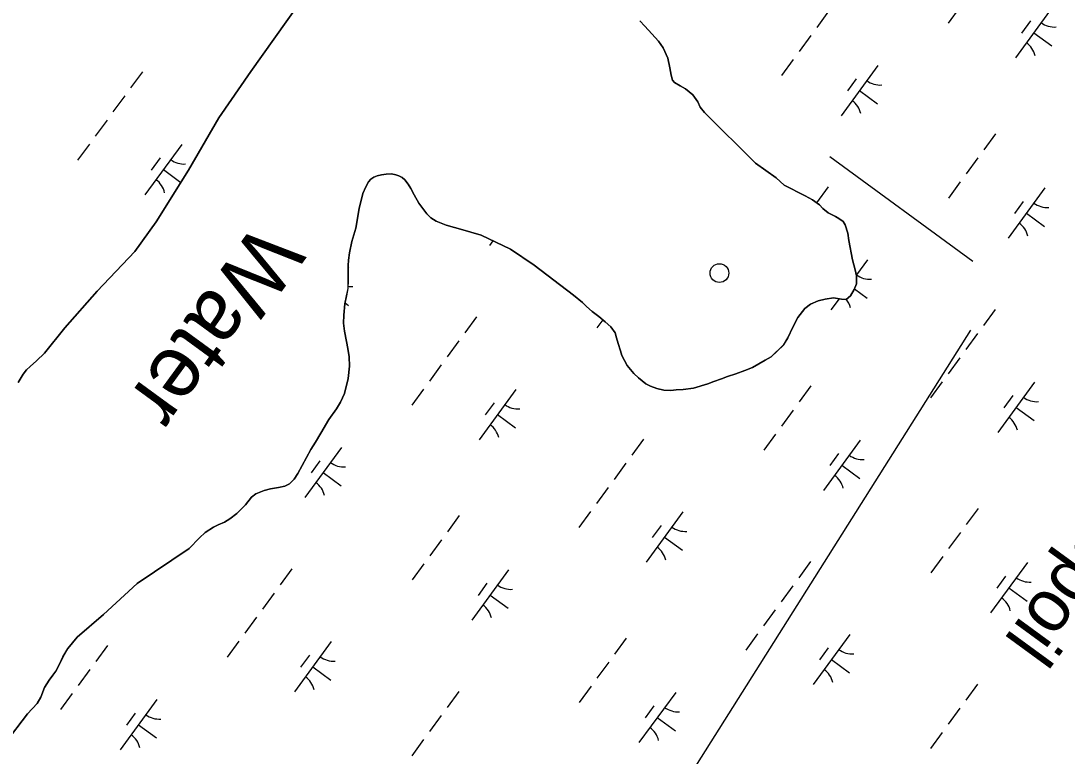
# Model space of a CAD drawing. Extents: x 3905714 to 3926767, y 183354 to 205755.
# Drawn here: x 3911390 to 3912230, y 188884 to 189474 of the extents above; entities that cross this region are included whole.
import ezdxf

# ---------------------------------------------------------------- set-up
doc = ezdxf.new("R2010")
doc.units = 0
for name, color, linetype in [('V-CHAN-SPOL', 7, 'Continuous'), ('V-DOMW-TANK', 7, 'Continuous'), ('V-RIVR-IDEN', 7, 'Continuous'), ('V-TOPO-SHOR', 7, 'Continuous'), ('V-UTIL-LINE', 7, 'Continuous'), ('V-WETL-SWMP', 7, 'Continuous')]:
    doc.layers.add(name, color=color, linetype=linetype)

msp = doc.modelspace()

# ---------------------------------------------------------------- linework, layer by layer
at = {"layer": 'V-DOMW-TANK'}
msp.add_circle((3911951, 189271.83), 7.5, dxfattribs=at)
at = {"layer": 'V-TOPO-SHOR'}
for points in [[(3911387.7, 189183.86), (3911391.77, 189190.6), (3911394.41, 189194.03), (3911397.44, 189196.94), (3911402.31, 189201.43), (3911408.9, 189207.65), (3911425.1, 189227.86), (3911451.19, 189257.2), (3911481.36, 189289.19), (3911498.48, 189312.83), (3911524.54, 189354.45), (3911548.89, 189396.58), (3911574.56, 189433.57), (3911613.01, 189487.34)], [(3911833.85, 189254.21), (3911841.12, 189248.15), (3911844.29, 189245.12), (3911848.92, 189240.91), (3911854.07, 189237.09), (3911859.35, 189232.61), (3911863.85, 189228.79), (3911867.16, 189223.78), (3911868.35, 189219.82), (3911869.81, 189215.34), (3911871.53, 189209.4), (3911872.73, 189205.58), (3911876.96, 189197.67), (3911882.25, 189191.21), (3911886.08, 189187.78), (3911892.03, 189182.91), (3911895.73, 189181.07), (3911900.61, 189179.23), (3911906.29, 189177.92), (3911912.1, 189177.53), (3911916.32, 189178.2), (3911921.99, 189178.47), (3911930.17, 189179.54), (3911941.78, 189182.99), (3911946.53, 189184.84), (3911952.73, 189186.96), (3911957.61, 189188.82), (3911964.2, 189191.07), (3911971.46, 189193.59), (3911977.52, 189196.11), (3911982.8, 189199.02), (3911987.81, 189201.93), (3911992.69, 189204.58), (3912002.44, 189214.09), (3912005.86, 189219.77), (3912010.07, 189228.49), (3912014.01, 189236.28), (3912019.68, 189243.29), (3912024.29, 189246.86), (3912030.36, 189249.51), (3912035.9, 189250.97), (3912042.76, 189251.9), (3912048.96, 189250.99), (3912052.79, 189250.73), (3912056.22, 189253.51), (3912059.24, 189258.66), (3912061.08, 189263.15), (3912061.21, 189269.48), (3912060.01, 189274.49), (3912058.02, 189282.54), (3912055.09, 189297.85), (3912054.03, 189303.78), (3912051.9, 189310.64), (3912050.45, 189313.15), (3912047.01, 189315.65), (3912044.37, 189317.23), (3912038.43, 189320.12), (3912034.07, 189323.68), (3912031.29, 189326.58), (3912025.75, 189330.53), (3912019.93, 189333.82), (3912002.9, 189342.37), (3911996.55, 189348.16), (3911979.91, 189360.15), (3911938.93, 189400.6), (3911935.63, 189404.95), (3911933.64, 189409.17), (3911929.67, 189414.97), (3911923.73, 189419.71), (3911919.37, 189422.21), (3911915.01, 189424.84), (3911913.42, 189426.69), (3911912.36, 189430.77), (3911911.16, 189436.58), (3911909.7, 189444.23), (3911905.73, 189452.54), (3911902.02, 189457.94), (3911896.73, 189463.87), (3911891.18, 189469.94), (3911887.08, 189474.42)], [(3911377.29, 188894.54), (3911395.19, 188918.06), (3911402.97, 188926.39), (3911405.86, 188931.27), (3911408.75, 188939.2), (3911412.57, 188945.14), (3911415.47, 188948.97), (3911417.97, 188952.14), (3911420.73, 188957.3), (3911423.63, 188963.64), (3911427.58, 188970.37), (3911435.22, 188979.62), (3911456.17, 188997.73), (3911483.19, 189022.72), (3911524.97, 189050.76), (3911533.41, 189059.35), (3911537.89, 189063.58), (3911544.61, 189067.95), (3911548.43, 189069.8), (3911553.45, 189071.79), (3911557.79, 189074.43), (3911563.46, 189078.8), (3911570.45, 189085.8), (3911575.19, 189091.88), (3911578.62, 189094.66), (3911585.34, 189097.18), (3911590.35, 189098.64), (3911596.95, 189099.83), (3911601.96, 189100.9), (3911605.66, 189102.75), (3911609.35, 189106.32), (3911612.37, 189110.81), (3911619.35, 189123.89), (3911622.9, 189130.23), (3911626.59, 189136.04), (3911630.93, 189143.44), (3911637.38, 189154.4), (3911643.44, 189162.72), (3911646.73, 189168.27), (3911649.88, 189175.14), (3911652.9, 189187.28), (3911653.94, 189197.18), (3911653.66, 189204.71), (3911652.46, 189211.17), (3911651.4, 189216.84), (3911649.94, 189225.15), (3911649.13, 189231.62), (3911649.25, 189237.95), (3911650.17, 189247.06), (3911651.34, 189253.66), (3911652.66, 189259.34), (3911652.91, 189265.93), (3911652.9, 189273.06), (3911652.76, 189277.81), (3911653.01, 189282.3), (3911653.79, 189287.98), (3911655.76, 189297.22), (3911658.91, 189307.78), (3911661.53, 189323.75), (3911664.67, 189335.63), (3911666.91, 189341.18), (3911669.01, 189345.14), (3911670.99, 189347.26), (3911673.5, 189348.71), (3911676.13, 189349.77), (3911679.56, 189350.57), (3911683.39, 189351.23), (3911687.61, 189351.37), (3911691.04, 189350.72), (3911693.55, 189349.93), (3911696.06, 189348.48), (3911698.31, 189346.64), (3911701.09, 189343.21), (3911703.07, 189339.65), (3911705.72, 189334.64), (3911709.55, 189328.05), (3911715.9, 189319.48), (3911719.08, 189316.19), (3911723.57, 189313.42), (3911731.49, 189310.4), (3911744.83, 189306.59), (3911751.29, 189304.76), (3911759.61, 189302.26), (3911783.12, 189290.95), (3911802.27, 189278.05), (3911833.85, 189254.21)]]:
    msp.add_lwpolyline(points, dxfattribs=at)
at = {"layer": 'V-UTIL-LINE'}
for points in [[(3912039.73, 189365.45), (3912154.46, 189281.34)], [(3911441.15, 188098.33), (3912152.99, 189225.97)]]:
    msp.add_lwpolyline(points, dxfattribs=at)
at = {"layer": 'V-WETL-SWMP'}
for p, q in [((3911613.01, 189487.34), (3911574.56, 189433.57)), ((3912144.1, 189485.29), (3912134.64, 189472.38)), ((3912218.28, 189484.96), (3912188.73, 189444.63)), ((3912038.68, 189482), (3912029.23, 189469.09)), ((3911887.08, 189474.42), (3911891.18, 189469.94)), ((3911891.18, 189469.94), (3911896.73, 189463.87)), ((3912200.83, 189474.19), (3912193.73, 189464.51)), ((3911896.73, 189463.87), (3911902.02, 189457.94)), ((3912024.5, 189462.64), (3912015.04, 189449.73)), ((3912203.5, 189464.79), (3912218.02, 189454.15)), ((3911902.02, 189457.94), (3911905.73, 189452.54)), ((3911905.73, 189452.54), (3911909.7, 189444.23)), ((3911909.7, 189444.23), (3911911.16, 189436.58)), ((3912010.32, 189443.28), (3912000.86, 189430.37)), ((3911487.48, 189433.41), (3911478.02, 189420.5)), ((3911574.56, 189433.57), (3911548.89, 189396.58)), ((3911911.16, 189436.58), (3911912.36, 189430.77)), ((3912078.32, 189438.44), (3912048.77, 189398.11)), ((3911912.36, 189430.77), (3911913.42, 189426.69)), ((3911913.42, 189426.69), (3911915.01, 189424.84)), ((3911915.01, 189424.84), (3911919.37, 189422.21)), ((3912060.87, 189427.68), (3912053.78, 189418)), ((3911919.37, 189422.21), (3911923.73, 189419.71)), ((3911923.73, 189419.71), (3911929.67, 189414.97)), ((3912063.55, 189418.28), (3912078.07, 189407.64)), ((3911473.3, 189414.05), (3911463.84, 189401.14)), ((3911929.67, 189414.97), (3911933.64, 189409.17)), ((3911933.64, 189409.17), (3911935.63, 189404.95)), ((3911935.63, 189404.95), (3911938.93, 189400.6)), ((3911938.93, 189400.6), (3911979.91, 189360.15)), ((3911459.11, 189394.69), (3911449.66, 189381.78)), ((3911548.89, 189396.58), (3911524.54, 189354.45)), ((3912172.86, 189383.69), (3912163.41, 189370.78)), ((3911444.93, 189375.33), (3911435.47, 189362.42)), ((3911519.11, 189375), (3911489.56, 189334.67)), ((3911501.66, 189364.24), (3911494.57, 189354.56)), ((3911979.91, 189360.15), (3911996.55, 189348.16)), ((3912158.68, 189364.33), (3912149.22, 189351.42)), ((3911524.54, 189354.45), (3911498.48, 189312.83)), ((3911504.34, 189354.84), (3911518.35, 189344.57)), ((3911676.13, 189349.77), (3911673.5, 189348.71)), ((3911679.56, 189350.57), (3911676.13, 189349.77)), ((3911683.39, 189351.24), (3911679.56, 189350.57)), ((3911687.61, 189351.37), (3911683.39, 189351.24)), ((3911691.04, 189350.72), (3911687.61, 189351.37)), ((3911693.55, 189349.93), (3911691.04, 189350.72)), ((3911696.06, 189348.48), (3911693.55, 189349.93)), ((3911666.91, 189341.18), (3911664.68, 189335.63)), ((3911669.02, 189345.14), (3911666.91, 189341.18)), ((3911670.99, 189347.26), (3911669.02, 189345.14)), ((3911673.5, 189348.71), (3911670.99, 189347.26)), ((3911698.31, 189346.64), (3911696.06, 189348.48)), ((3911701.09, 189343.21), (3911698.31, 189346.64)), ((3911703.07, 189339.65), (3911701.09, 189343.21)), ((3911996.55, 189348.16), (3912002.9, 189342.37)), ((3912002.9, 189342.37), (3912019.93, 189333.82)), ((3912038.33, 189340.93), (3912029.01, 189328.2)), ((3912144.5, 189344.97), (3912135.04, 189332.06)), ((3911664.68, 189335.63), (3911661.53, 189323.75)), ((3911705.72, 189334.64), (3911703.07, 189339.65)), ((3911709.56, 189328.05), (3911705.72, 189334.64)), ((3912019.93, 189333.82), (3912025.74, 189330.53)), ((3912212.5, 189340.14), (3912182.95, 189299.8)), ((3911715.9, 189319.48), (3911709.56, 189328.05)), ((3912025.74, 189330.53), (3912031.29, 189326.58)), ((3912031.29, 189326.58), (3912034.07, 189323.68)), ((3912195.05, 189329.37), (3912187.96, 189319.69)), ((3911661.53, 189323.75), (3911658.91, 189307.78)), ((3911719.08, 189316.19), (3911715.9, 189319.48)), ((3911723.57, 189313.42), (3911719.08, 189316.19)), ((3912034.07, 189323.68), (3912038.43, 189320.12)), ((3912038.43, 189320.12), (3912044.37, 189317.23)), ((3912044.37, 189317.23), (3912047.01, 189315.65)), ((3912047.01, 189315.65), (3912050.45, 189313.15)), ((3912197.73, 189319.97), (3912212.25, 189309.33)), ((3911498.48, 189312.83), (3911481.36, 189289.18)), ((3911658.91, 189307.78), (3911655.76, 189297.22)), ((3911731.49, 189310.4), (3911723.57, 189313.42)), ((3911744.82, 189306.59), (3911731.49, 189310.4)), ((3912050.45, 189313.15), (3912051.91, 189310.64)), ((3912051.91, 189310.64), (3912054.03, 189303.78)), ((3911751.29, 189304.76), (3911744.82, 189306.59)), ((3911759.61, 189302.26), (3911751.29, 189304.76)), ((3911783.12, 189290.95), (3911759.61, 189302.26)), ((3912054.03, 189303.78), (3912055.09, 189297.85)), ((3911655.76, 189297.22), (3911653.8, 189287.98)), ((3911769.03, 189297.73), (3911766.28, 189293.98)), ((3911802.27, 189278.05), (3911783.12, 189290.95)), ((3912055.09, 189297.85), (3912058.02, 189282.54)), ((3911481.36, 189289.18), (3911451.19, 189257.2)), ((3911653.01, 189282.3), (3911652.76, 189277.81)), ((3911653.8, 189287.98), (3911653.01, 189282.3)), ((3912058.02, 189282.54), (3912060.01, 189274.49)), ((3912069.96, 189282.52), (3912061.01, 189270.3)), ((3911652.76, 189277.81), (3911652.9, 189273.06)), ((3911653.29, 189276.7), (3911652.81, 189276.04)), ((3911833.85, 189254.21), (3911802.27, 189278.05)), ((3912060.01, 189274.49), (3912061.21, 189269.48)), ((3911652.91, 189265.94), (3911652.65, 189259.34)), ((3911652.9, 189273.06), (3911652.91, 189265.94)), ((3912061.21, 189269.48), (3912061.08, 189263.15)), ((3911451.19, 189257.2), (3911425.1, 189227.86)), ((3911652.65, 189259.34), (3911651.34, 189253.66)), ((3912059.25, 189258.66), (3912056.22, 189253.51)), ((3912061.08, 189263.15), (3912059.25, 189258.66)), ((3912059.47, 189259.22), (3912069.71, 189251.72)), ((3911651.34, 189253.66), (3911650.17, 189247.06)), ((3911841.12, 189248.15), (3911833.85, 189254.21)), ((3912030.36, 189249.51), (3912024.29, 189246.86)), ((3912035.9, 189250.97), (3912030.36, 189249.51)), ((3912042.76, 189251.9), (3912035.9, 189250.97)), ((3912047.07, 189251.27), (3912040.41, 189242.19)), ((3912048.96, 189250.99), (3912042.76, 189251.9)), ((3912052.79, 189250.73), (3912048.96, 189250.99)), ((3912056.22, 189253.51), (3912052.79, 189250.73)), ((3911650.17, 189247.06), (3911649.26, 189237.95)), ((3911650.31, 189247.89), (3911653.04, 189245.89)), ((3911844.29, 189245.12), (3911841.12, 189248.15)), ((3911848.92, 189240.91), (3911844.29, 189245.12)), ((3911854.07, 189237.09), (3911848.92, 189240.91)), ((3912019.68, 189243.29), (3912014.02, 189236.28)), ((3912024.29, 189246.86), (3912019.68, 189243.29)), ((3912172.51, 189242.62), (3912163.06, 189229.72)), ((3911649.26, 189237.95), (3911649.13, 189231.62)), ((3911649.13, 189231.62), (3911649.94, 189225.15)), ((3911755.84, 189236.8), (3911746.38, 189223.89)), ((3911857.27, 189234.38), (3911852.55, 189227.93)), ((3911859.36, 189232.61), (3911854.07, 189237.09)), ((3911863.85, 189228.79), (3911859.36, 189232.61)), ((3912014.02, 189236.28), (3912010.07, 189228.49)), ((3911425.1, 189227.86), (3911408.9, 189207.65)), ((3911649.94, 189225.15), (3911651.4, 189216.84)), ((3911867.16, 189223.78), (3911863.85, 189228.79)), ((3911868.35, 189219.82), (3911867.16, 189223.78)), ((3912010.07, 189228.49), (3912005.86, 189219.77)), ((3912158.33, 189223.26), (3912148.87, 189210.36)), ((3911651.4, 189216.84), (3911652.46, 189211.17)), ((3911741.66, 189217.44), (3911732.2, 189204.53)), ((3911869.81, 189215.34), (3911868.35, 189219.82)), ((3911871.53, 189209.4), (3911869.81, 189215.34)), ((3912005.86, 189219.77), (3912002.44, 189214.1)), ((3911408.9, 189207.65), (3911402.31, 189201.43)), ((3911652.46, 189211.17), (3911653.66, 189204.7)), ((3911872.73, 189205.58), (3911871.53, 189209.4)), ((3912002.44, 189214.1), (3911992.69, 189204.58)), ((3911402.31, 189201.43), (3911397.44, 189196.94)), ((3911653.66, 189204.7), (3911653.94, 189197.18)), ((3911727.47, 189198.08), (3911718.02, 189185.17)), ((3911876.96, 189197.67), (3911872.73, 189205.58)), ((3911982.8, 189199.02), (3911977.52, 189196.11)), ((3911987.81, 189201.93), (3911982.8, 189199.02)), ((3911992.69, 189204.58), (3911987.81, 189201.93)), ((3912144.14, 189203.9), (3912134.69, 189191)), ((3911391.77, 189190.6), (3911387.69, 189183.86)), ((3911394.41, 189194.03), (3911391.77, 189190.6)), ((3911397.44, 189196.94), (3911394.41, 189194.03)), ((3911653.94, 189197.18), (3911652.9, 189187.28)), ((3911882.25, 189191.21), (3911876.96, 189197.67)), ((3911886.08, 189187.78), (3911882.25, 189191.21)), ((3911964.2, 189191.07), (3911957.61, 189188.82)), ((3911971.46, 189193.59), (3911964.2, 189191.07)), ((3911977.52, 189196.11), (3911971.46, 189193.59)), ((3911652.9, 189187.28), (3911649.88, 189175.14)), ((3911892.03, 189182.91), (3911886.08, 189187.78)), ((3911895.73, 189181.07), (3911892.03, 189182.91)), ((3911900.61, 189179.23), (3911895.73, 189181.07)), ((3911941.78, 189182.99), (3911930.17, 189179.54)), ((3911946.53, 189184.84), (3911941.78, 189182.99)), ((3911952.73, 189186.96), (3911946.53, 189184.84)), ((3911957.61, 189188.82), (3911952.73, 189186.96)), ((3912024.55, 189181.25), (3912015.09, 189168.35)), ((3912129.96, 189184.54), (3912120.5, 189171.64)), ((3912204.14, 189184.22), (3912174.59, 189143.88)), ((3911649.88, 189175.14), (3911646.73, 189168.27)), ((3911713.29, 189178.72), (3911703.83, 189165.81)), ((3911787.47, 189178.39), (3911757.92, 189138.06)), ((3911906.29, 189177.92), (3911900.61, 189179.23)), ((3911912.1, 189177.53), (3911906.29, 189177.92)), ((3911916.32, 189178.2), (3911912.1, 189177.53)), ((3911921.99, 189178.47), (3911916.32, 189178.2)), ((3911930.17, 189179.54), (3911921.99, 189178.47)), ((3912186.69, 189173.45), (3912179.6, 189163.77)), ((3911646.73, 189168.27), (3911643.44, 189162.72)), ((3911770.02, 189167.62), (3911762.93, 189157.94)), ((3911643.44, 189162.72), (3911637.38, 189154.4)), ((3911772.7, 189158.22), (3911787.22, 189147.59)), ((3912010.36, 189161.89), (3912000.91, 189148.99)), ((3912189.37, 189164.05), (3912203.89, 189153.41)), ((3911637.38, 189154.4), (3911630.93, 189143.44)), ((3911630.93, 189143.44), (3911626.59, 189136.04)), ((3911996.18, 189142.53), (3911986.72, 189129.63)), ((3911647.52, 189131.88), (3911617.97, 189091.54)), ((3911626.59, 189136.04), (3911622.9, 189130.23)), ((3911890.02, 189138.49), (3911880.56, 189125.59)), ((3912064.19, 189137.7), (3912034.64, 189097.37)), ((3911619.35, 189123.89), (3911612.37, 189110.81)), ((3911622.9, 189130.23), (3911619.35, 189123.89)), ((3912046.74, 189126.93), (3912039.64, 189117.25)), ((3911630.06, 189121.11), (3911622.97, 189111.43)), ((3911875.83, 189119.13), (3911866.38, 189106.23)), ((3912049.41, 189117.53), (3912063.93, 189106.9)), ((3911609.35, 189106.32), (3911605.66, 189102.75)), ((3911612.37, 189110.81), (3911609.35, 189106.32)), ((3911632.74, 189111.71), (3911647.26, 189101.07)), ((3911585.34, 189097.18), (3911578.62, 189094.66)), ((3911590.35, 189098.64), (3911585.34, 189097.18)), ((3911596.95, 189099.83), (3911590.35, 189098.64)), ((3911601.96, 189100.9), (3911596.95, 189099.83)), ((3911605.66, 189102.75), (3911601.96, 189100.9)), ((3911861.65, 189099.77), (3911852.19, 189086.87)), ((3911575.19, 189091.88), (3911570.45, 189085.8)), ((3911578.62, 189094.66), (3911575.19, 189091.88)), ((3911570.45, 189085.8), (3911563.46, 189078.8)), ((3911847.47, 189080.41), (3911838.01, 189067.51)), ((3912158.73, 189082.95), (3912149.27, 189070.04)), ((3911553.45, 189071.79), (3911548.43, 189069.8)), ((3911557.8, 189074.43), (3911553.45, 189071.79)), ((3911563.46, 189078.8), (3911557.8, 189074.43)), ((3911742.05, 189077.12), (3911732.6, 189064.21)), ((3911921.65, 189080.08), (3911892.1, 189039.75)), ((3911537.89, 189063.58), (3911533.41, 189059.35)), ((3911544.61, 189067.95), (3911537.89, 189063.58)), ((3911548.43, 189069.8), (3911544.61, 189067.95)), ((3911904.2, 189069.32), (3911897.11, 189059.64)), ((3912144.54, 189063.59), (3912135.09, 189050.68)), ((3911533.41, 189059.35), (3911524.97, 189050.76)), ((3911727.87, 189057.76), (3911718.41, 189044.85)), ((3911906.88, 189059.92), (3911921.4, 189049.28)), ((3911524.97, 189050.76), (3911483.18, 189022.72)), ((3911713.69, 189038.4), (3911704.23, 189025.49)), ((3912024.2, 189040.19), (3912014.74, 189027.28)), ((3912130.36, 189044.23), (3912120.9, 189031.32)), ((3912198.37, 189039.39), (3912168.82, 188999.06)), ((3911607.53, 189034.36), (3911598.07, 189021.46)), ((3911781.7, 189033.57), (3911752.15, 188993.24)), ((3911483.18, 189022.72), (3911456.17, 188997.73)), ((3911764.24, 189022.8), (3911757.15, 189013.12)), ((3912180.92, 189028.63), (3912173.82, 189018.95)), ((3911593.34, 189015), (3911583.88, 189002.1)), ((3911766.92, 189013.4), (3911781.44, 189002.76)), ((3912010.01, 189020.83), (3912000.56, 189007.92)), ((3912183.59, 189019.23), (3912198.11, 189008.59)), ((3911456.17, 188997.73), (3911435.22, 188979.62)), ((3911995.83, 189001.47), (3911986.37, 188988.56)), ((3911579.16, 188995.64), (3911569.7, 188982.74)), ((3911435.22, 188979.62), (3911427.58, 188970.37)), ((3911981.65, 188982.11), (3911972.19, 188969.2)), ((3912055.83, 188981.78), (3912026.28, 188941.45)), ((3911459.56, 188972.99), (3911450.11, 188960.08)), ((3911564.97, 188976.28), (3911555.52, 188963.38)), ((3911639.16, 188975.95), (3911609.61, 188935.62)), ((3911876.23, 188978.82), (3911866.78, 188965.91)), ((3912038.38, 188971.01), (3912031.28, 188961.33)), ((3911423.63, 188963.63), (3911420.73, 188957.3)), ((3911427.58, 188970.37), (3911423.63, 188963.63)), ((3911621.7, 188965.19), (3911614.61, 188955.51)), ((3911420.73, 188957.3), (3911417.97, 188952.14)), ((3911624.38, 188955.79), (3911638.9, 188945.15)), ((3911862.05, 188959.46), (3911852.59, 188946.55)), ((3912041.05, 188961.61), (3912055.57, 188950.97)), ((3911415.47, 188948.97), (3911412.57, 188945.14)), ((3911417.97, 188952.14), (3911415.47, 188948.97)), ((3911445.38, 188953.63), (3911435.92, 188940.72)), ((3911408.75, 188939.2), (3911405.86, 188931.27)), ((3911412.57, 188945.14), (3911408.75, 188939.2)), ((3911847.87, 188940.1), (3911838.41, 188927.19)), ((3912158.38, 188941.88), (3912148.92, 188928.97)), ((3911405.86, 188931.27), (3911402.97, 188926.39)), ((3911431.19, 188934.27), (3911421.74, 188921.36)), ((3911499.2, 188929.44), (3911469.65, 188889.11)), ((3911741.7, 188936.06), (3911732.25, 188923.15)), ((3911915.88, 188935.26), (3911886.32, 188894.93)), ((3911402.97, 188926.39), (3911395.2, 188918.06)), ((3911898.42, 188924.5), (3911891.33, 188914.82)), ((3912144.19, 188922.52), (3912134.74, 188909.61)), ((3911395.2, 188918.06), (3911377.28, 188894.54)), ((3911481.75, 188918.67), (3911474.66, 188908.99)), ((3911727.52, 188916.7), (3911718.06, 188903.79)), ((3911901.1, 188915.1), (3911915.62, 188904.46)), ((3911484.43, 188909.27), (3911498.95, 188898.63)), ((3911713.34, 188897.34), (3911703.88, 188884.43)), ((3912130.01, 188903.16), (3912120.55, 188890.25))]:
    msp.add_line(p, q, dxfattribs=at)
for centre, start, end in [((3912220.02, 189486.93), 232.99998, 274.54364), ((3912187.37, 189442.37), 12.99998, 54.54364), ((3912080.07, 189440.42), 232.99998, 274.54364), ((3912047.42, 189395.86), 12.99998, 54.54364), ((3911520.85, 189376.98), 232.99998, 274.54364), ((3911488.2, 189332.41), 12.99998, 54.54364), ((3912214.24, 189342.11), 232.99998, 274.54364), ((3912181.6, 189297.55), 12.99998, 54.54364), ((3912071.71, 189284.5), 232.99998, 274.54364), ((3911655.03, 189278.67), 262.47847, 274.54364), ((3912039.06, 189239.93), 12.99998, 38.17607), ((3911789.21, 189180.37), 232.99998, 274.54364), ((3912205.88, 189186.19), 232.99998, 274.54364), ((3912173.24, 189141.63), 12.99998, 54.54364), ((3911756.56, 189135.8), 12.99998, 54.54364), ((3912065.93, 189139.68), 232.99998, 274.54364), ((3911649.26, 189133.85), 232.99998, 274.54364), ((3912033.28, 189095.11), 12.99998, 54.54364), ((3911616.61, 189089.29), 12.99998, 54.54364), ((3911923.39, 189082.06), 232.99998, 274.54364), ((3911890.74, 189037.5), 12.99998, 54.54364), ((3911783.44, 189035.54), 232.99998, 274.54364), ((3912200.11, 189041.37), 232.99998, 274.54364), ((3911750.79, 188990.98), 12.99998, 54.54364), ((3912167.46, 188996.81), 12.99998, 54.54364), ((3911640.9, 188977.93), 232.99998, 274.54364), ((3912057.57, 188983.75), 232.99998, 274.54364), ((3911608.25, 188933.37), 12.99998, 54.54364), ((3912024.92, 188939.19), 12.99998, 54.54364), ((3911917.62, 188937.24), 232.99998, 274.54364), ((3911500.94, 188931.41), 232.99998, 274.54364), ((3911884.97, 188892.68), 12.99998, 54.54364), ((3911468.29, 188886.85), 12.99998, 54.54364)]:
    msp.add_arc(centre, 17.62, start, end, dxfattribs=at)

# ---------------------------------------------------------------- texts
at = {"layer": 'V-CHAN-SPOL'}
msp.add_text('Spoil', height=42, rotation=233.87144, dxfattribs=at).set_placement((3912252.42, 189078.28))
at = {"layer": 'V-RIVR-IDEN'}
msp.add_text('Water', height=50, rotation=233.87144, dxfattribs=at).set_placement((3911579.36, 189314.3))

doc.saveas('drawing.dxf')
